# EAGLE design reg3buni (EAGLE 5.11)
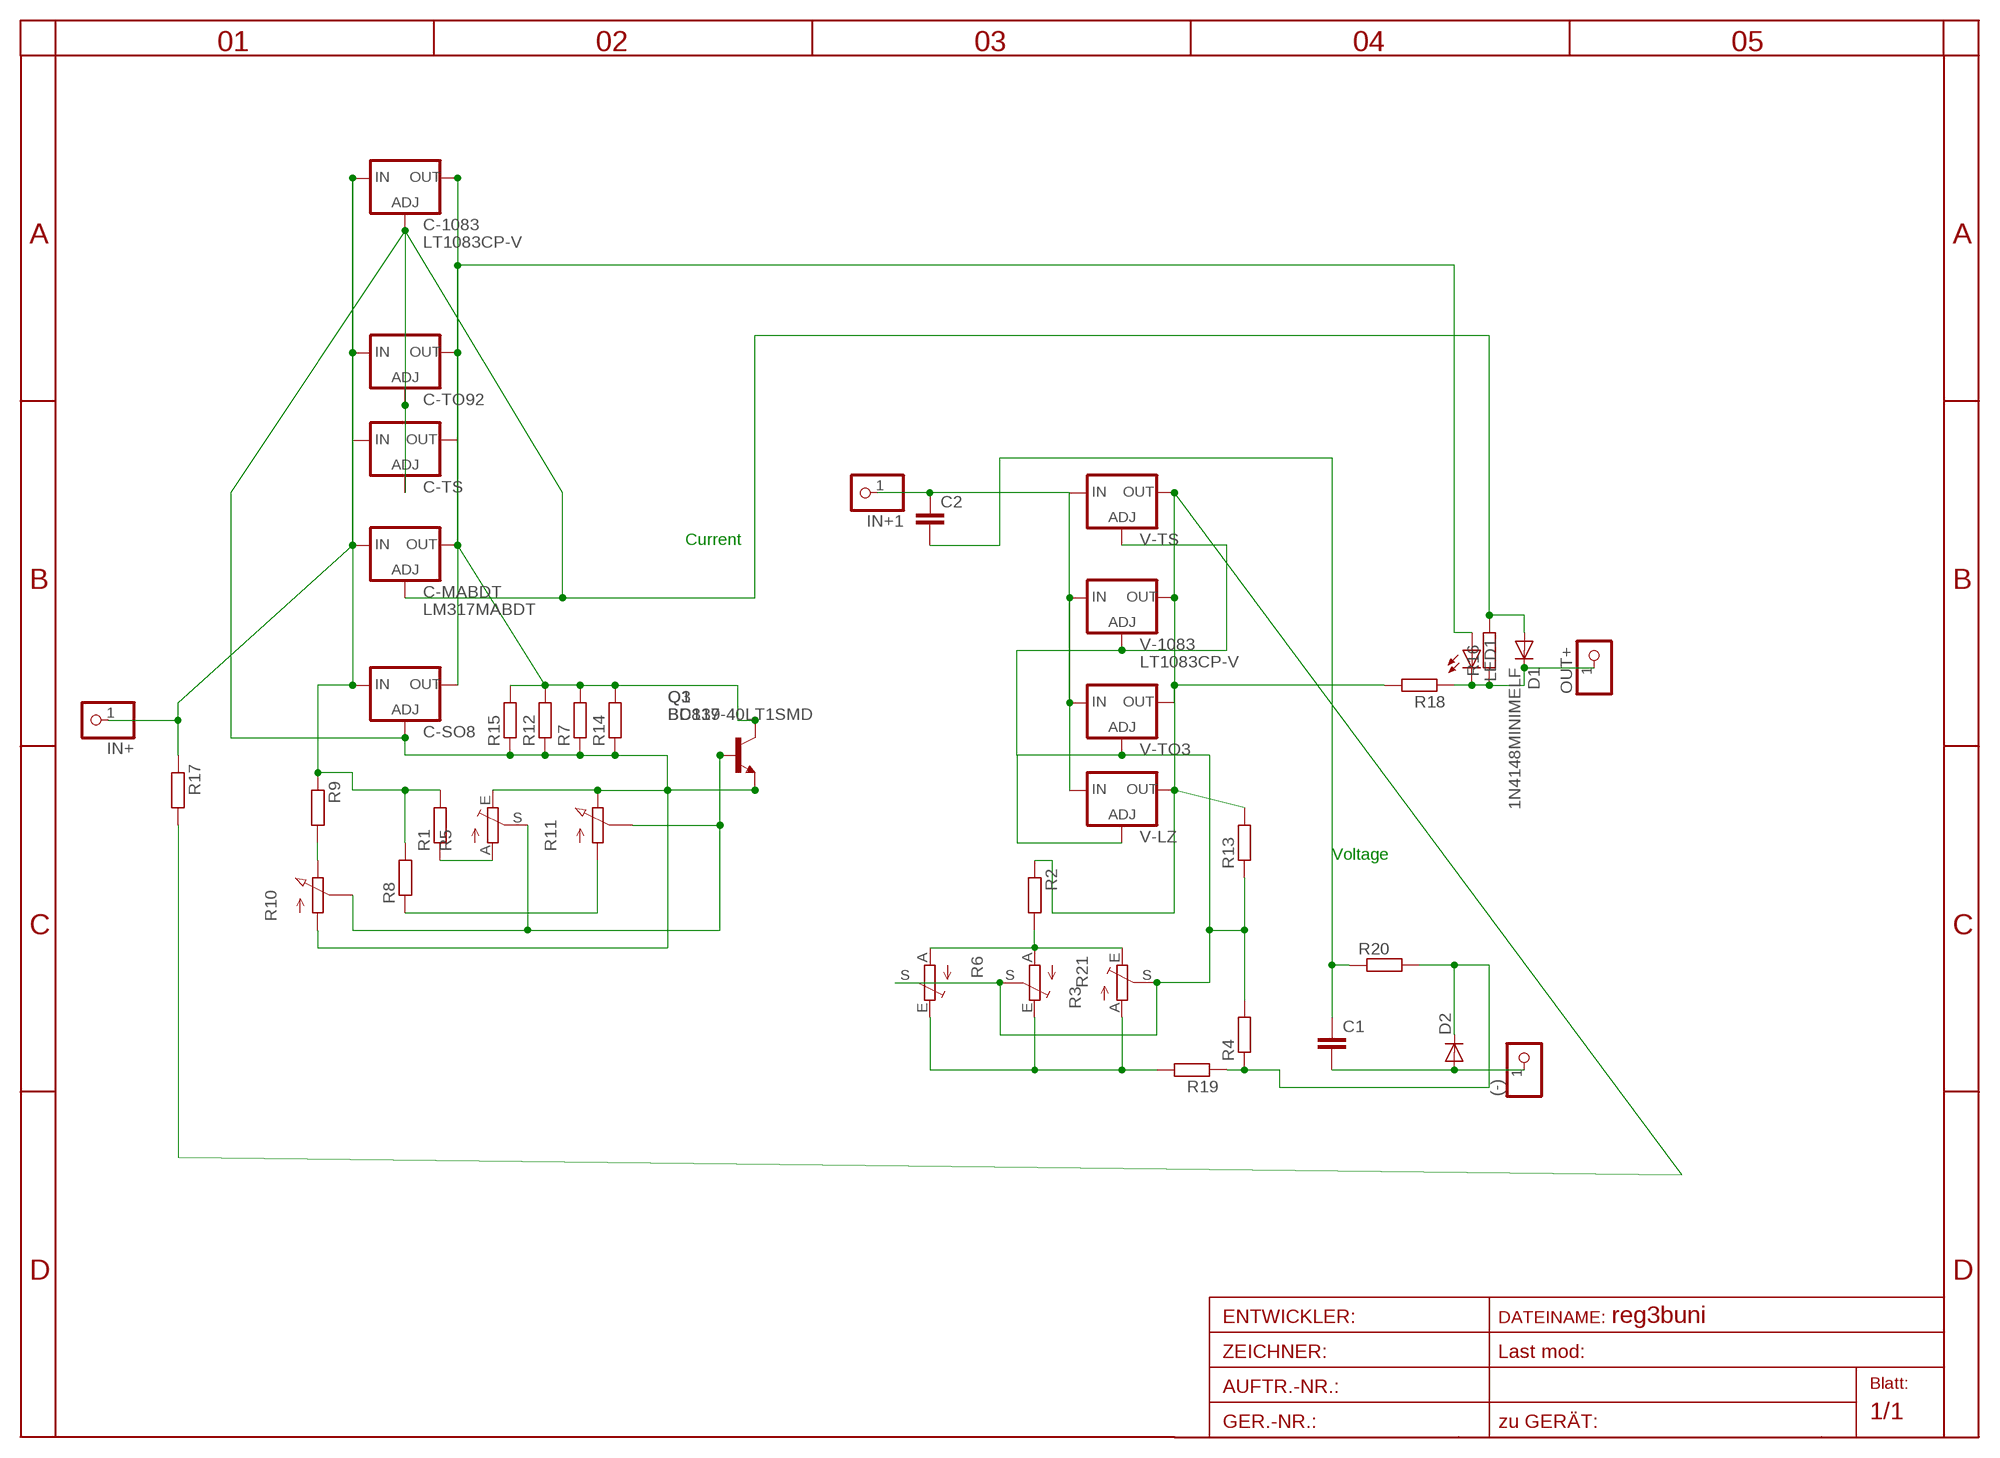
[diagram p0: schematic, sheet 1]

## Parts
(-)  PINHD-1X1  [1X01]
C1  C-EU050-025X075  [C050-025X075]
C2  C-EU050-025X075  [C050-025X075]
C-1083  LT1083CP-V  [TO247S]
C-MABDT  LM317MABDT  [DPACK]
C-SO8  LM317LM-OUTPIN7  [SO08]
C-TO92  LM317LZ  [317L]
C-TS  LM317TS  [317TS]
D1  1N4148MINIMELF  [MINIMELF]
D2  DIODE-MINIMELF  [MINIMELF]
IN+  PINHD-1X1  [1X01]
IN+1  PINHD-1X1  [1X01]
LED1  LEDCHIPLED_1206  [CHIPLED_1206]
OUT+  PINHD-1X1  [1X01]
Q1  BC817-40LT1SMD  [SOT23-BEC]
Q3  BD139  [TO126V]
R1  R-EU_0207/15  [0207/15]
R2  R-EU_0207/12  [0207/12]
R3  TRIM_EU-S64W  [S64W]
R4  R-EU_0204/7  [0204/7]
R5  TRIM_EU-S64W  [S64W]
R6  TRIM_EU-RAND160  [RANDL]
R7  R-EU_R1206  [R1206]
R8  R-EU_R1206  [R1206]
R9  R-EU_R1206  [R1206]
R10  PC25  [PC25]
R11  PC25  [PC25]
R12  R-EU_R1206  [R1206]
R13  R-EU_0204/5  [0204/5]
R14  R-EU_R1206  [R1206]
R15  R-EU_R1206  [R1206]
R16  R-EU_R0402  [R0402]
R17  R-EU_R0402  [R0402]
R18  R-EU_R0402  [R0402]
R19  R-EU_R0402  [R0402]
R20  R-EU_0207/12  [0207/12]
R21  TRIM_EU-EVND_H  [EVND8AA]
V-1083  LT1083CP-V  [TO247S]
V-LZ  LM317LZ  [317L]
V-TO3  LM317-TO3  [TO3-K02]
V-TS  LM317TS  [317TS]

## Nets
ADJ2: R3.S R4.2 R6.S R13.1 R21.S V-1083.1(ADJ) V-LZ.1(ADJ) V-TO3.2(ADJ) V-TS.1(ADJ)
ADJUST: C-1083.1(ADJ) C-MABDT.1(ADJ) C-SO8.4(ADJ) C-TO92.1(ADJ) C-TS.1(ADJ) D1.A Q1.E Q3.3(E) R5.E R7.1 R10.A R11.E R12.1 R14.1 R15.1 R16.2
B1: Q1.B Q3.1(B) R5.S R10.S R11.S
IN+1: C2.1 IN+1.1 V-1083.3(IN) V-LZ.3(IN) V-TO3.1(IN) V-TS.3(IN)
IN-: (-).1 C1.2 D2.A
INPUT+: C-1083.3(IN) C-MABDT.3(IN) C-SO8.1(IN) C-TO92.3(IN) C-TS.3(IN) IN+.1 R1.2 R8.2 R9.1 R17.1
MINUS: R1.1 R5.A
N$1: R3.A R6.E R19.2 R21.E
N$2: R2.2 R3.E R6.A R21.A
N$5: R8.1 R11.A
N$6: R9.2 R10.E
N$7: C1.1 C2.2 R20.1
OUT1: C-1083.2(OUT) C-MABDT.4(OUT) C-SO8.7(OUT) C-TO92.2(OUT) C-TS.2(OUT) LED1.A Q1.C Q3.2(C) R7.2 R12.2 R14.2 R15.2
OUT2: R2.1 R13.2 R17.2 R18.2 V-1083.2(OUT) V-LZ.2(OUT) V-TO3.3(OUT) V-TS.2(OUT)
OUT+: D1.C LED1.C OUT+.1 R16.1 R18.1
VIRT-: D2.C R4.1 R19.1 R20.2

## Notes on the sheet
- Current
- Voltage

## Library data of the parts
(-) IN+ IN+1 OUT+ = pinhead(2):PINHD-1X1: PIN HEADER
C1 C2 = rcl:C-EU: CAPACITOR, European symbol
C-1083 V-1083 = linear-technology-2:LT1083*: 7.5A Low Dropout Positive Adjustable Regulators
C-MABDT = v-reg:LM317?*: 500 mA Adjustable Output Positive Voltage Regulator Source: http://www.onsemi.co.jp .. LM317M-D.PDF
C-SO8 C-TO92 V-LZ = v-reg-3:LM317L: Adjustable Voltage Regulator, 1.2V to 37V, 100mA
C-TS V-TS = v-reg:LM317TS: VOLTAGE REGULATOR
D1 = diode-1:1N4148: DIODE
D2 = diode:DIODE-: DIODE
LED1 = led:LED: LED
Q1 = transistor-npn:BC817*: NPN Transistor
Q3 = transistor-npn:BD139*: NPN Transistor
R1 R2 R4 R7-R9 R12-R20 = rcl-2:R-EU_: RESISTOR, European symbol
R3 R5 R6 R21 = pot:TRIM_EU-: POTENTIOMETER
R10 R11 = pot-vitrohm:PC25: VITROHM POTENTIOMETER
V-TO3 = v-reg:LM317-TO3: VOLTAGE REGULATOR

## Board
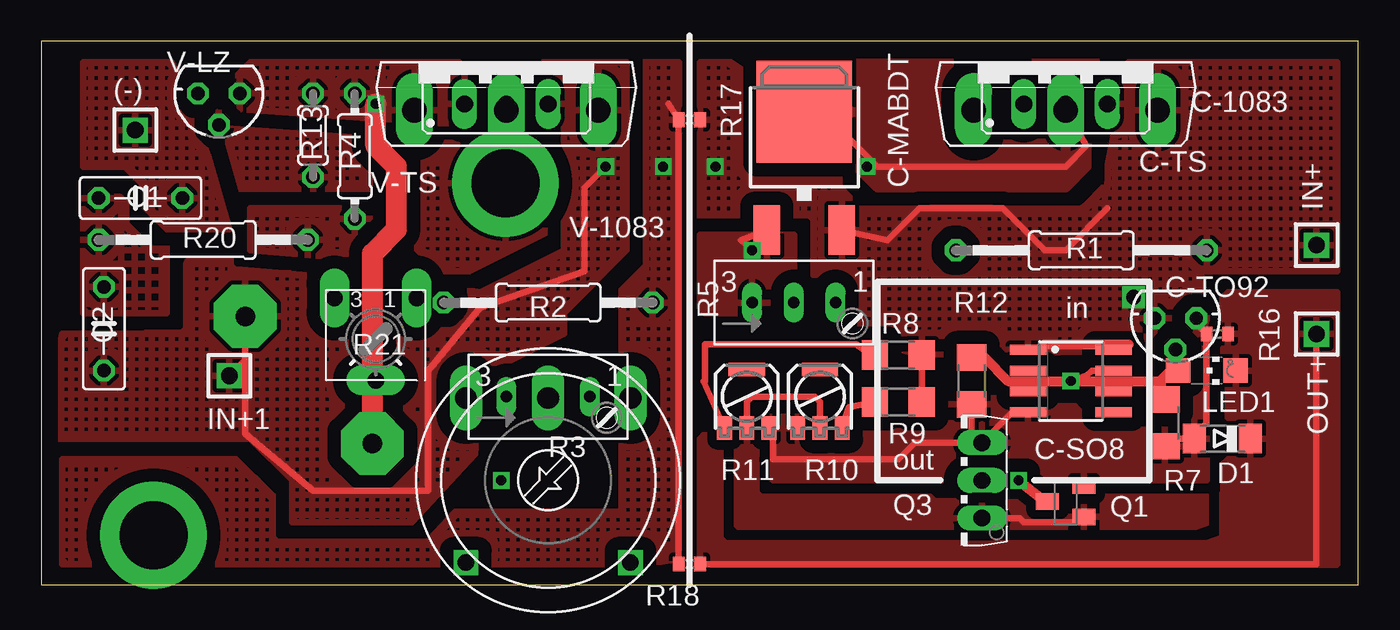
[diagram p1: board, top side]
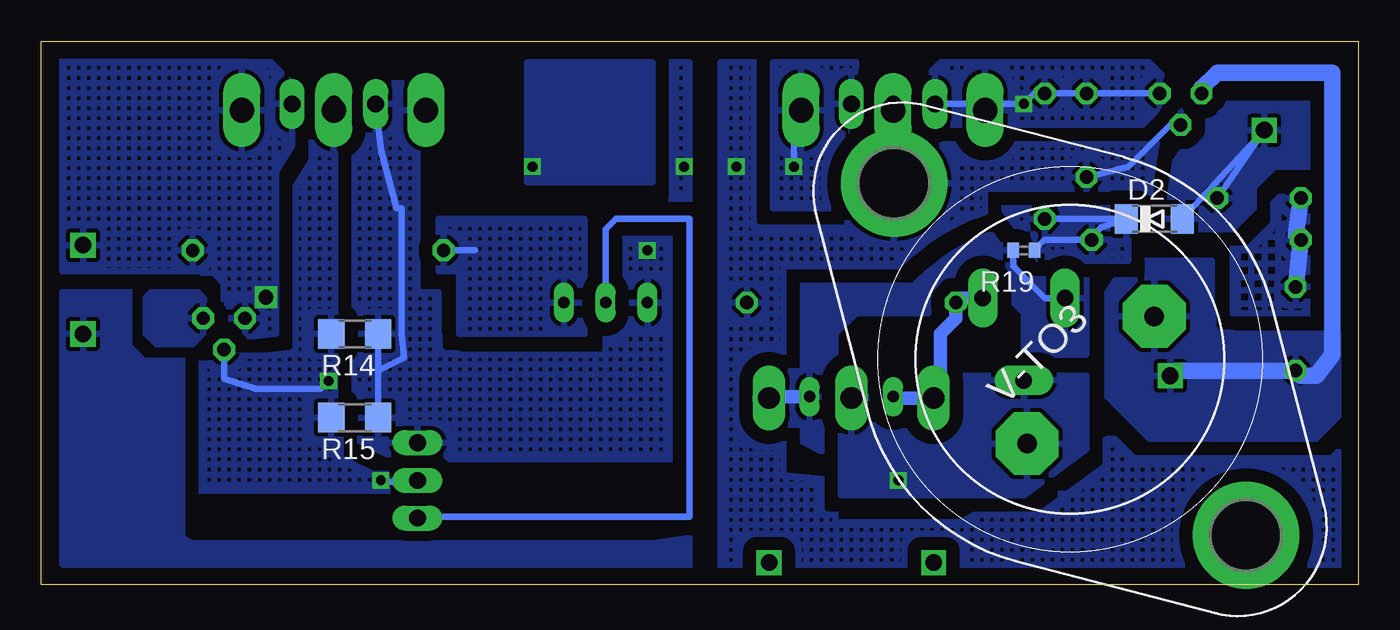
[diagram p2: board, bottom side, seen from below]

Size 80.01 x 33.02 mm. Coordinates in mm from the lower left corner, seen from the top.
Outline: 0,0 80.01,0 80.01,33.02 0,33.02 0,0
Copper layers (1*16): Top 0.035mm / dielectric 1.5mm / Bottom 0.035mm
Design rules "default": minimum track width 10mil, minimum drill 24mil, track to track 8mil, track to pad 8mil, pad to pad 8mil, via to via 8mil, smd to smd 8mil, copper to edge 40mil, drill to drill 8mil, minimum pad ring 10mil, minimum via ring 8mil, stop-mask expansion 4mil, vias tented up to drill 0mil, thermal gap 10mil

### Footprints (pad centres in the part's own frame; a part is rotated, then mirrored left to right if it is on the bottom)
1X01 = drill 1.016 square: 1 0,0
C050-025X075 = drill 0.813 octagon: 1 -2.54,0; 2 2.54,0
TO247S = drill 1.499 long: 1 -5.588,-2.921; 2 0,-2.921; 3 5.588,-2.921
DPACK = smd 1.6 x 3: 1 -2.28,-4.8; 3 2.28,-4.8 | smd 5.8 x 6.2: 4 0,2.38
SO08 = smd 0.6 x 2.2: 1 -1.905,-2.6; 2 -0.635,-2.6; 3 0.635,-2.6; 4 1.905,-2.6; 5 1.905,2.6; 6 0.635,2.6; 7 -0.635,2.6; 8 -1.905,2.6
317L = drill 0.813 octagon: 1 -1.27,0; 2 0,1.905; 3 1.27,0
317TS = drill 1.016 long: 1 -2.54,-2.54; 2 0,-2.54; 3 2.54,-2.54
MINIMELF = smd 1.4 x 1.8: A 1.7,0; C -1.7,0
CHIPLED_1206 = smd 1.5 x 1.5: A 0,-1.75; C 0,1.75
SOT23-BEC = smd 1 x 1.4: B -0.95,-1.1; C 0,1.1; E 0.95,-1.1
TO126V = drill 1.016 long: 1 -2.286,-1.27; 2 0,-1.27; 3 2.286,-1.27
0207/15 = drill 0.813 octagon: 1 -7.62,0; 2 7.62,0
0207/12 = drill 0.813 octagon: 1 -6.35,0; 2 6.35,0
S64W = drill 0.7 long: A 2.54,1.27; E -2.54,1.27; S 0,1.27
0204/7 = drill 0.813 octagon: 1 -3.81,0; 2 3.81,0
RANDL = drill 1.321 long: A -5,5; E 5,5; S 0,5 | drill 1 square: P$1 -5,-5; P$2 5,-5
R1206 = smd 1.6 x 1.803: 1 -1.422,0; 2 1.422,0
PC25 = smd 2.2 x 0.8: 4 0,1.65 | smd 0.9 x 1.4: A -1.35,-1.9; E 1.35,-1.9; S 0,-1.9
0204/5 = drill 0.813 octagon: 1 -2.54,0; 2 2.54,0
R0402 = smd 0.7 x 0.9: 1 -0.65,0; 2 0.65,0
EVND8AA = drill 1 pad 1.778 long: A -2.5,-2.5; E 2.5,-2.5; S 0,2.5
TO3-K02 = drill 1.194 pad 3.81 octagon: 1 -1.778,-5.461; 2 -1.778,5.461 | drill 4.115 pad 6.477 round: 3 15.113,0; 3@ -15.113,0

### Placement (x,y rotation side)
(-)  5.71,27.62 0 top
C1  6.03,23.5 0 top
C2  3.81,15.56 90 top
C-1083  62.23,31.75 0 top
C-MABDT  46.35,26.35 0 top
C-SO8  62.55,12.38 270 top
C-TO92  68.9,16.19 180 top
C-TS  62.23,31.75 0 top
D1  71.75,8.89 180 top
D2  12.38,22.23 0 bottom
IN+  77.47,20.64 0 top
IN+1  11.43,12.7 0 top
LED1  70.8,13.02 270 top
OUT+  77.47,15.24 0 top
Q1  62.23,5.08 90 top
Q3  55.88,6.35 90 top
R1  63.18,20.32 0 top
R2  30.8,17.14 180 top
R3  30.8,10.16 0 top
R4  19.05,26.04 90 top
R5  45.72,15.88 0 top
R6  30.8,6.35 0 top
R7  68.26,9.84 90 top
R8  52.07,13.97 0 top
R9  52.07,11.11 180 top
R10  47.31,11.43 0 top
R11  42.86,11.43 0 top
R12  56.52,12.38 90 top
R13  16.51,27.3 270 top
R14  60.96,15.24 180 bottom
R15  60.96,10.16 180 bottom
R16  71.44,15.24 180 top
R17  39.37,28.26 180 top
R18  39.37,1.27 180 top
R19  20.32,20.32 180 bottom
R20  9.84,20.95 0 top
R21  20.32,14.92 180 top
V-1083  28.26,31.75 0 top
V-LZ  10.79,29.84 180 top
V-TO3  17.52,13.71 135 bottom
V-TS  28.26,31.75 0 top

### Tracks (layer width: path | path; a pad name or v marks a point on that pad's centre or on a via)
ADJ2  (via drill 0.6)
  Top 1.27: V-TO3.2 20.12,20.12 21.59,21.59 21.59,25.4 20.32,26.67 v20.32,29.21
  Bottom 0.406: V-LZ.1 R13.1 R4.2 19.68,29.84 v20.32,29.21 21.59,29.21 22.32,28.48 | 22.32,28.48 V-1083.1 23.05,29.21 V-TS.1 | 22.32,28.48 21.78,27.94
  other vias: 27.94,6.35
  pour Bottom (isolate 0.813, hatched): 11.43,30.48 12.7,31.75 25.4,31.75 26.67,30.48 26.67,29.21 25.4,27.94 12.7,27.94
  pour Bottom (isolate 0.813, rank 2): 16.51,12.7 31.43,12.7 31.43,5.46 20.32,5.46 16.51,8.26
  pour Top (isolate 0.813, hatched): 11.43,30.48 12.7,31.75 25.4,31.75 26.67,30.48 26.67,29.21 25.4,27.94 12.06,28.89
ADJUST  (via drill 0.6)
  Top 0.406: C-SO8.4 58.99,10.48 Q3.3 | Q3.3 57.09,8.57 | R12.1 56.52,9.27 Q3.3 | C-MABDT.1 42.51,20.92 v43.18,20.32 | C-TO92.1 70.17,15.86 R16.2 70.79,9.83 69.85,8.89 68.43,8.89 R7.1 | R11.E 44.45,9.29 44.45,7.62 52.07,7.62 53.09,8.64 Q3.3
  Bottom 0.406: 59.69,10.01 R15.1 59.54,13.02 | C-TS.1 59.37,26.35 58.42,22.86 58.1,22.86 58.1,15.24 57.95,13.8 59.54,13.02 | 59.54,13.02 R14.1 | 57.15,8.89 57.4,8.89
  pour Bottom (isolate 0.813, rank 4, hatched): 45.72,22.23 40.64,22.23 40.64,7.62 58.42,7.62 60.96,8.89 60.96,30.48 57.15,30.48 57.15,17.78 55.88,17.78 55.88,15.24 54.61,13.97 45.72,13.97
  pour Top (isolate 0.813): 40.01,21.27 45.72,21.27 45.72,16.51 40.32,16.51 40.01,16.83
  pour Top (isolate 0.813): 44.45,11.43 44.45,6.35 70.8,6.35 70.8,16.83 67.31,11.43 66.04,10.16 63.5,10.16 62.23,11.43
  pour Bottom (isolate 0.61): 69.85,16.51 69.85,17.14 70.48,17.78 73.34,17.78 73.66,17.46 73.66,15.24 73.03,14.61 70.8,14.61 70.17,15.24
B1
  Top 0.406: Q1.B 63.01,3.81 59.69,3.81 59.44,4.06 Q3.1 | R11.S 42.86,11.11 43.18,11.43 46.99,11.43 47.31,11.11 R10.S
  Bottom 0.406: R5.S 45.72,21.59 45.09,22.23 40.64,22.23 40.64,4.13 57.15,4.13 Q3.1
  pour Top (isolate 0.61, rank 3): 41.91,10.16 41.91,2.54 69.85,2.54 71.12,3.81 71.12,5.08 70.48,5.71 65.09,5.71 64.45,5.08 54.29,5.08 53.66,5.71 45.4,5.71 44.13,6.99 44.13,10.48
IN+1  (via drill 0.6)
  Top 0.406: v34.29,25.4 33.02,24.13 33.02,19.05 26.67,16.83 23.5,13.02 23.5,5.71 16.51,5.71 12.4,9.19 V-TO3.1 12.4,13.67 IN+1.1
  Bottom 0.406: 11.11,13.02 IN+1.1 | 3.49,12.7 C2.1 | v34.29,25.4 34.29,28.38 V-1083.3
  Bottom 1.016: C2.1 11.11,13.02 | V-LZ.3 9.53,30.16 8.57,31.11 1.59,31.11 1.59,13.97 2.54,12.7 3.49,12.7
  pour Bottom (isolate 0.813, hatched): 30.48,31.75 35.56,31.75 35.56,22.86 31.75,22.86
  pour Top (isolate 0.813, rank 3, hatched): 1.27,15.24 6.35,15.24 8.89,19.68 15.24,19.68 26.67,17.78 31.75,20.32 31.75,30.48 30.48,31.75 35.56,31.75 35.56,20.32 31.75,16.51 31.75,15.24 26.67,12.7 26.35,7.94 22.54,3.81 15.24,3.81 15.24,6.35 12.7,8.89 0,8.89
  pour Bottom (isolate 0.813, rank 3): 15.24,17.78 15.24,11.43 12.7,8.89 2.54,8.89 0,11.43 0,13.97 1.27,15.24 7.62,15.24 8.89,16.51 8.89,19.68 13.97,19.68
IN-
  Bottom 0.406: C1.2 (-).1 D2.A
  pour Bottom (isolate 0.813): 2.54,29.21 8.89,29.21 9.84,27.62 11.11,25.72 11.75,21.59 7.62,21.59 6.35,22.86 6.35,24.13 5.08,25.4 2.54,25.4
  pour Top (isolate 0.813, hatched): 2.54,31.75 7.94,31.75 10.16,26.04 11.43,21.59 7.62,21.59 6.35,22.86 6.35,24.13 5.08,25.4 2.54,25.4
INPUT+  (via drill 0.6, 0.9)
  Top 0.406: R9.1 R8.2 | C-SO8.1 60.64,14.29 60.96,14.61 | C-MABDT.3 51.4,20.92 53.34,22.86 58.42,22.86 60.96,20.32 62.23,20.32 64.77,22.86
  Top 0.61: 60.96,14.61 66.04,14.61
  other vias: 66.36,17.46 40.96,25.4
  pour Top (isolate 0.813, rank 5, hatched): 66.04,31.75 78.74,31.75 78.74,19.05 70.48,19.05 70.48,14.29 53.34,13.97 46.35,15.88 46.35,21.59 40.01,21.59 40.01,31.75 41.91,31.75 53.34,24.13 64.77,24.13 64.77,25.4
  pour Bottom (isolate 0.813, rank 2, hatched): 66.36,31.75 78.74,32.07 78.74,19.05 70.17,19.05 70.17,17.78 68.58,14.92 65.72,15.24 65.72,25.08 64.77,26.67 64.77,30.48 66.04,31.75
  pour Bottom (isolate 0.813, rank 5, hatched): 40.64,31.75 40.64,22.86 42.55,22.86 42.55,31.75
MINUS
  Bottom 0.406: R1.1 53.66,20.32
  pour Bottom (isolate 0.813, rank 3, hatched): 46.99,22.23 55.88,22.23 55.88,19.05 54.61,19.05 54.61,15.24 46.99,15.24
N$1
  Bottom 0.406: R21.E 19.05,17.42 20.95,19.37 R19.2
  Bottom 0.813: R3.A 35.72,11.43 R6.E
  pour Bottom (isolate 0.813, rank 6): 37.15,10.48 34.61,18.1 33.02,19.05 26.67,19.05 24.13,21.59 19.05,21.59 16.51,19.05 16.51,13.97 20.32,13.97 20.32,16.51 21.59,17.78 24.13,17.78 25.4,16.51 30.48,16.51 31.75,15.24 31.75,7.62
N$2
  Bottom 0.813: R21.A 24.17,17.42 R2.2 24.45,16.19 25.4,15.24 25.4,11.75 R6.A 28.18,11.35 R3.E
N$5
  Top 0.406: R8.1 50.65,13.8 49.53,14.61 40.32,14.61 40.32,12.38 40.24,12.38 R11.A
N$6
  Top 0.406: R10.E 49.07,10.8 R9.2
N$7
  Bottom 0.406: R20.1 3.81,21.27
  Bottom 1.016: C2.2 R20.1 | 3.81,21.27 C1.1
  pour Bottom (isolate 0.813, rank 2, hatched): 2.54,24.13 2.54,16.51 7.62,16.51 7.62,22.86
  pour Top (isolate 0.813, rank 2, hatched): 2.54,24.13 2.54,16.51 7.62,16.51 7.62,22.86
OUT1  (via drill 0.6)
  Top 0.406: C-MABDT.4 48.1,28.1 50.8,25.4 62.23,25.4 63.5,26.67 C-1083.2 | 60.96,5.08 Q1.C | v62.55,12.38 63.5,12.7 63.82,13.02 C-SO8.7 | R7.2 68.11,12.38 67.94,12.38 | R12.2 57.32,13.8 | 68.58,13.02 LED1.A
  Top 0.61: v59.37,6.35 60.96,5.08 | 57.32,13.8 58.74,12.38 v62.55,12.38 67.94,12.38 68.58,13.02
  Bottom 0.406: v59.37,6.35 57.47,6.03 Q3.2 | C-TO92.2 68.9,12.53 66.99,11.9 63.03,11.9 v62.55,12.38
  other vias: 50.16,25.4
  pour Bottom (isolate 0.813, rank 5, hatched): 62.55,28.89 64.45,29.53 65.41,22.23 65.41,14.29 69.22,14.29 70.48,13.65 70.8,5.71 57.47,5.71
  pour Top (isolate 0.813, rank 3): 49.53,31.75 64.77,31.75 63.5,29.21 63.5,25.4 62.23,24.13 50.8,24.13 49.53,25.4
  pour Bottom (isolate 0.813, rank 4): 42.86,31.75 42.86,24.45 50.48,24.45 50.48,31.75
OUT2  (via drill 0.6)
  Top 0.406: 38.1,29.21 R17.2 R18.2
  Bottom 0.406: V-LZ.2 11.43,27.94 13.97,25.4 R13.2 | v37.78,25.4 38.1,25.4 | V-TO3.3 28.2,28.77 V-1083.2 V-TS.2
  pour Bottom (isolate 0.813, rank 4, hatched): 10.16,29.21 12.7,29.21 13.97,27.94 29.21,27.94 31.75,25.4 31.75,24.13 33.02,22.86 35.56,22.86 35.56,31.75 38.73,31.75 38.73,0.32 1.27,0 0,0 0,8.89 15.24,8.89 24.13,3.81 31.75,3.81 31.75,6.35 34.92,6.67 34.92,19.37 27.94,19.37 arc38 20.32,23.18 11.43,22.86 10.16,24.13
  pour Top (isolate 0.813, rank 4, hatched): 10.16,29.21 12.7,29.21 13.97,27.94 29.21,27.94 31.75,25.4 31.75,24.13 33.02,22.86 35.56,22.86 35.56,31.75 38.73,31.75 38.73,1.59 36.83,1.27 1.27,1.27 1.27,7.62 13.97,7.62 14.61,4.45 35.24,4.45 35.24,20.32 34.29,20.32 33.02,19.05 24.13,19.05 20.32,22.86 11.43,22.86 10.16,24.13
OUT+
  Top 0.406: OUT+.1 77.47,1.27 R18.1
  pour Top (isolate 0.61, rank 2): 72.07,17.78 78.74,17.78 78.74,1.27 78.11,0.64 40.64,0.64 40.01,1.27 40.01,8.89 40.32,9.21 40.96,9.21 41.27,8.89 41.27,2.86 41.59,2.54 70.8,2.54 71.75,2.86 71.75,7.3 72.07,7.62 73.03,7.62 73.03,10.16 72.07,10.16 72.07,13.34 71.75,13.65 71.75,17.46
  pour Bottom (isolate 0.61, rank 2): 71.44,17.78 78.74,17.78 78.74,1.27 78.11,0.64 40.64,0.64 40.64,2.86 42.86,2.54 70.8,2.54 71.44,2.86
VIRT-
  Bottom 0.406: R19.1 19.07,20.95 R20.2 15.67,21.7 D2.C R4.1
  pour Bottom (isolate 0.813, hatched): 13.97,22.86 21.59,22.86 19.37,19.68 13.97,19.68
  pour Top (isolate 0.813, hatched): 12.7,22.86 20.32,22.86 20.32,19.68 12.7,20.32

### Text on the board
tNames: in | out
